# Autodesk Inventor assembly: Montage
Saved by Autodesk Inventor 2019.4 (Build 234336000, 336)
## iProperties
Created: 2021-06
Part Number: Montage
Document SubType Name: Assembly
Designer: Administrator
Title: Montage v24
Author: Administrator
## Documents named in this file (20)
- c:\worker\convert-fusion-r04\tmp\job-1\39\output\files\e1e84fd7-b652-4e3d-a1c7-f0a54bbc30a7\e4684e8f-2a16-4933-8dd1-5f3cda3001b2.iam
- c:\worker\convert-fusion-r04\tmp\job-1\39\output\files\e1e84fd7-b652-4e3d-a1c7-f0a54bbc30a7\Zentrierblock v7.ipt
- c:\worker\convert-fusion-r04\tmp\job-1\39\output\files\e1e84fd7-b652-4e3d-a1c7-f0a54bbc30a7\Faceplate v7.ipt
- c:\worker\convert-fusion-r04\tmp\job-1\39\output\files\e1e84fd7-b652-4e3d-a1c7-f0a54bbc30a7\Sockel v9.ipt
- c:\worker\convert-fusion-r04\tmp\job-1\39\output\files\e1e84fd7-b652-4e3d-a1c7-f0a54bbc30a7\Montage v22_Schieber v16 v2.ipt
- c:\worker\convert-fusion-r04\tmp\job-1\39\output\files\e1e84fd7-b652-4e3d-a1c7-f0a54bbc30a7\Zentrierteil v10.ipt
- c:\worker\convert-fusion-r04\tmp\job-1\39\output\files\e1e84fd7-b652-4e3d-a1c7-f0a54bbc30a7\HI_WUERTH 5094503012 parallel pin ISO 8734 3m6x12 Blank.ipt
- c:\worker\convert-fusion-r04\tmp\job-1\39\output\files\e1e84fd7-b652-4e3d-a1c7-f0a54bbc30a7\Zylinderkopfschraube DIN 912 M4x20 v2.iam
- c:\worker\convert-fusion-r04\tmp\job-1\39\output\files\e1e84fd7-b652-4e3d-a1c7-f0a54bbc30a7\Zylinderkopfschraube DIN 912 M4x20 v2_1.iam
- c:\worker\convert-fusion-r04\tmp\job-1\39\output\files\e1e84fd7-b652-4e3d-a1c7-f0a54bbc30a7\Zylinderkopfschraube DIN 912 M4x20 v2_2.iam
- c:\worker\convert-fusion-r04\tmp\job-1\39\output\files\e1e84fd7-b652-4e3d-a1c7-f0a54bbc30a7\Zylinderkopfschraube DIN 912 M4x20 v2_3.iam
- c:\worker\convert-fusion-r04\tmp\job-1\39\output\files\e1e84fd7-b652-4e3d-a1c7-f0a54bbc30a7\Hohe Rändelschraube M3 (gewinde gekürzt v3.iam
- c:\worker\convert-fusion-r04\tmp\job-1\39\output\files\e1e84fd7-b652-4e3d-a1c7-f0a54bbc30a7\Flache Rändelschraube M4x10 v2.iam
- c:\worker\convert-fusion-r04\tmp\job-1\39\output\files\e1e84fd7-b652-4e3d-a1c7-f0a54bbc30a7\Flache Rändelschraube M4x10 v2_1.iam
- c:\worker\convert-fusion-r04\tmp\job-1\39\output\files\e1e84fd7-b652-4e3d-a1c7-f0a54bbc30a7\Hohe Rändelschraube M5 v2.iam
- c:\worker\convert-fusion-r04\tmp\job-1\39\output\files\e1e84fd7-b652-4e3d-a1c7-f0a54bbc30a7\Hohe Rändelschraube M5 v2_1.iam
- c:\worker\convert-fusion-r04\tmp\job-1\39\output\files\e1e84fd7-b652-4e3d-a1c7-f0a54bbc30a7\HI_WUERTH 5094502020 parallel pin ISO 8734 2m6x20 Blank.ipt
- c:\worker\convert-fusion-r04\tmp\job-1\39\output\files\e1e84fd7-b652-4e3d-a1c7-f0a54bbc30a7\HI_WUERTH 5094502020 parallel pin ISO 8734 2m6x20 Blank (1).ipt
- c:\worker\convert-fusion-r04\tmp\job-1\39\output\files\e1e84fd7-b652-4e3d-a1c7-f0a54bbc30a7\_Spring plunger with thread locking  GN 615.3-M3-K-PFB (unbetätigt).ipt
- c:\worker\convert-fusion-r04\tmp\job-1\39\output\files\e1e84fd7-b652-4e3d-a1c7-f0a54bbc30a7\_WUERTH 0412926 washer DIN 9021 6.4 A4 BLK.ipt
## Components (19 placed, 14 different names)
1. Zentrierblock v7:1
2. Faceplate v7:1
3. Sockel v9:1
4. Montage v22_Schieber v16 v2:1
5. Zentrierteil v10:1
6. HI_WUERTH 5094503012 parallel pin ISO 8734 3m6x12 Blank:1
7. Zylinderkopfschraube DIN 912 M4x20 v2:1 [sub-assembly]
8. Zylinderkopfschraube DIN 912 M4x20 v2:2 [sub-assembly]
9. Zylinderkopfschraube DIN 912 M4x20 v2:3 [sub-assembly]
10. Zylinderkopfschraube DIN 912 M4x20 v2:4 [sub-assembly]
11. Hohe Rändelschraube M3 (gewinde gekürzt v3:1 [sub-assembly]
12. Flache Rändelschraube M4x10 v2:1 [sub-assembly]
13. Flache Rändelschraube M4x10 v2:2 [sub-assembly]
14. Hohe Rändelschraube M5 v2:2 [sub-assembly]
15. Hohe Rändelschraube M5 v2:3 [sub-assembly]
16. HI_WUERTH 5094502020 parallel pin ISO 8734 2m6x20 Blank:1
17. HI_WUERTH 5094502020 parallel pin ISO 8734 2m6x20 Blank (1):1
18. _Spring plunger with thread locking  GN 615.3-M3-K-PFB (unbetätigt):1
19. _WUERTH 0412926 washer DIN 9021 6.4 A4 BLK:1
